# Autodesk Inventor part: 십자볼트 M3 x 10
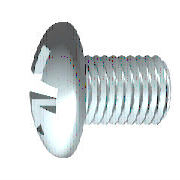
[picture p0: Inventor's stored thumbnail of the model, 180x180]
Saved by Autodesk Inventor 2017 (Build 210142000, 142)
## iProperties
IsCustomPart: 0
Created: 2012-02
Part Number: 십자볼트 M3 x 10
Material: 스테인리스강
Description: 십자 오목 머리 나사
Document SubType Name: Modeling
Standard: KS B 1023
Designer: mduedu
Standards Organization: KS
Language: ko-KR
Size Designation: A  M 3 x 10 - H
Categories: <MemberInstance><Categories><Category DisplayName="조임쇠" InternalName="e4da775c-781d-43d5-af7c-5136215cf5a6" Mnemonic="FSTN"><Category DisplayName="볼트" InternalN
Density: 1 g/cm^3
Appearance: 반광택
Author: mduedu
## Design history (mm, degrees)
body "Solid1"
workplane "Work Plane3"
sketch "스케치2"
  geometry: L1 (-3.72, 0)-(3.72, 0) reference; L2 (0, -3.72)-(0, 3.72) reference; L3 (0, 1.5)-(0, 0); L4 (0, 0)-(1.5, 0); L5 (0, 0)-(1.879, 1.879); L6 (0.253, 1.479)-(0.261, 0.456); L7 (1.479, 0.253)-(0.456, 0.261); L8 (0.253, -1.479)-(0.261, -0.456); L9 (1.479, -0.253)-(0.456, -0.261); L10 (-0.253, 1.479)-(-0.261, 0.456); L11 (-1.479, 0.253)-(-0.456, 0.261); L12 (-1.479, -0.253)-(-0.456, -0.261); L13 (-0.253, -1.479)-(-0.261, -0.456); A1 r 0.45 centre (0, 0) between (0.45, 0) and (0, 0.45); A2 r 1.5 centre (0, 0) between (1.5, 0) and (1.479, 0.253); A3 r 1.5 centre (0, 0) between (0.253, 1.479) and (0, 1.5); A4 r 1.5 centre (0, 0) between (1.479, 0.253) and (0.253, 1.479); A5 r 1.5 centre (0, 0) between (0, -1.5) and (0.253, -1.479); A6 r 1.5 centre (0, 0) between (0.253, -1.479) and (1.479, -0.253); A7 r 1.5 centre (0, 0) between (1.479, -0.253) and (1.5, 0); A8 r 1.5 centre (0, 0) between (-1.479, 0.253) and (-1.5, 0); A9 r 1.5 centre (0, 0) between (-0.253, 1.479) and (-1.479, 0.253); A10 r 1.5 centre (0, 0) between (0, 1.5) and (-0.253, 1.479); A11 r 1.5 centre (0, 0) between (-1.5, 0) and (-1.479, -0.253); A12 r 1.5 centre (0, 0) between (-1.479, -0.253) and (-0.253, -1.479); A13 r 1.5 centre (0, 0) between (-0.253, -1.479) and (0, -1.5); A14 r 0.525 centre (0, 0) between (0.525, 0) and (0, 0.525); A15 r 0.197 centre (0.457, 0.457) between (0.261, 0.456) and (0.456, 0.261); A16 r 0.197 centre (0.457, -0.457) between (0.456, -0.261) and (0.261, -0.456); A17 r 0.197 centre (-0.457, 0.457) between (-0.456, 0.261) and (-0.261, 0.456); A18 r 0.197 centre (-0.457, -0.457) between (-0.261, -0.456) and (-0.456, -0.261); 1 further point
  constraints: 38 point on circle, 22 end point, 19 symmetric about line, 18 centre point, 4 coincident, 3 collinear, 3 point on line, 3 tangent, 1 perpendicular, 21 other
  dimensions: "d4" = 45 deg angle of L5 L4; "d5" = 0.9 diameter of A1 (= 0.3 x SDM); "d6" = 3 diameter of A4 (= SDM); "d7" = 0.2525 distance from line of L6.start L3 (= 0.5 x SBR); "d14" = 1.05 diameter of A14 (= 0.35 x SDM)
extrude "슬롯" join sketch "스케치2" taper "d15" = 5 deg; stored distance "d54" = 10
revolve "절단부" stored, may be unused: angle "d56" = 90 deg
revolve "본체" stored, may be unused: angle "d18" = 90 deg
workplane "Work Plane1"
sketch "스케치1"
  geometry: L1 (10, 0)-(10, 1.5); L2 (10, 1.5)-(1, 1.5); L3 (3.962, 5.08)-(3.962, 5.08); L4 (-2.4, 0)-(-2.4, 2.59); L5 (-2.2, 1.4)-(-1.036, 0.82); L6 (-1.036, 0.82)-(-0.6, 0); L7 (-0.6, 0)-(10, 0); L8 (-5.105, 0)-(12.517, 0) reference; L9 (0, -1.016)-(0, 6.096) reference; L10 (-2.2, 1.4)-(-2.4, 1.5); L11 (-1.636, 2.657)-(-2.4, 2.59); L12 (-1.636, 2.657)-(0, 2.8); L13 (0, 2.8)-(0, 1.347); L14 (0, 1.347)-(0.693, 1.347); L15 (0.693, 1.347)-(1, 1.5); L16 (1, 1.5)-(0, 1.5); A1 r 5 centre (2.6, 0) between (-1.636, 2.657) and (-2.4, 0)
  constraints: 28 end point, 5 point on line, 4 collinear, 4 point on circle, 3 parallel, 2 perpendicular, 1 centre point, 1 horizontal, 1 tangent
  dimensions: "d1" = 3 diameter of L2 L7 (= GD); "d2" = 1.8 distance from line of L6.end L4 (= STI); "d11" = 3 diameter of L10.end L7 (= SDM); "d12" = 62 deg angle of L6 L7; "d13" = 26.5 deg angle of L5 L7; "d17" = 5.6 diameter of L12.end L7 (= KOD); "d19" = 5 deg angle of L12 L7 (= KEWI); "d20" = 2.4 distance between parallel lines of L4 L13 (= KOH); "d21" = 5 radius of A1 (= KR); "d23" = 2.6935 diameter of L14 L7 (= BDM); "d24" = 9 distance of L1.end L2.end (= GEL); "d25" = 0.30673 horizontal distance of L14.end L2.end (= GAL); "d28" = 10 distance between parallel lines of L1 L13 (= NLG)
fillet "모깎기1" dims "d29" = 1.2 (= RR)
fillet "모깎기2" dims "d16" = 0.101 (= 0.2 x SBR)
feature "스레드" dims "d8" = 9 (= GEL), "d9" = 0
chamfer "모따기1" distance "d26" = 0.30673 (= -0.5 x SPD + 0.5 x GD); stored, may be unused: second distance "d27" = 0.30683 (computed from GUL), angle "d78" = 45 deg
other parameters: "GD" = 3 (= NND) [user parameter; used in 2 equation terms], "NLG" = 10 [user parameter; used in 1 equation term], "GEL" = 9 [user parameter; used in 2 equation terms], "KOD" = 5.6 [user parameter; used in 1 equation term], "KOH" = 2.4 [user parameter; used in 2 equation terms], "SDM" = 3 [user parameter; used in 4 equation terms], "STI" = 1.8 [user parameter; used in 1 equation term], "SBR" = 0.505 [user parameter; used in 2 equation terms], "GAL" = 0.30673 (= 0.61345 x PTC) [user parameter; used in 1 equation term], "SPD" = 2.38655 (= NND - 1.2269 x PTC) [user parameter; used in 1 equation term], "KEWI" = 5 deg [user parameter; used in 1 equation term], "d3" = -2.4 (= -KOH), "d10" = 0, "KR" = 5 [user parameter; used in 1 equation term], "BDM" = 2.6935 [user parameter; used in 1 equation term], "GUL" = 0.30673 (= 0.61345 x PTC) [user parameter; used in 1 equation term], "RR" = 1.2 [user parameter; used in 1 equation term], "d79" = 0, "d80" = 0, "PTC" = 0.5 [user parameter; used in 5 equation terms], "THREADDIA" = 3 [user parameter; used in 1 equation term], "TOA" = 30 deg [user parameter], "NND" = 3 [user parameter; used in 2 equation terms], "GD1" = 2.38655 (= THREADDIA - 1.2269 x PTC) [user parameter]
